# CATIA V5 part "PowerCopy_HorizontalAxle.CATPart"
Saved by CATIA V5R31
Part number: HorizontalAxle
Bounding box of the stored display mesh (mm): x -30 to 30, y -5 to 5, z -4.99 to 4.99
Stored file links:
  C:\Users\patol451\OneDrive - Linköpings universitet\Nuvarande kurser\Exjobb\LampCATIA\PowerCopy_HorizontalAxle.CATPart
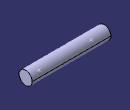
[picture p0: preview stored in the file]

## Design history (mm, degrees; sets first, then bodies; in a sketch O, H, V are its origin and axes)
Parameters
  diameter = 10 mm
  extraLength_OneSide = 10 mm
Set1 "References"
  Point1 "AxlePointLeft": (-20, 0, 0)
  Point2 "AxlePointRight": (20, 0, 0)
Set2 "Placement"
  Point3 "PlacementPoint1": type OnCurve, Support Line1, Ratio 0.5
  Point4 "PlacementPoint2": (0, 0, 0), relative to Point1
Set3 "Output"
  Point5 "OutputPoint1": (0, 0, 0), relative to Point1
  Point6 "OutputPoint2": (0, 0, 0), relative to Point2
  Point7 "OutputPoint3": type OnCurve, Support Line1, Ratio 0.5
Set4
  Line1: type PtPt, FirstPoint Point2, SecondPoint Point1
  Plane1: type Normal, Curve Line1, Ratio 0
  Circle1: type CenterAxis, Start 0, End 180, Pt Project1, Axis Line2, Radius 5 {= diameter /2}
  Plane2: type OffsetPt, RefPlane Plane1, RefPoint Point2
  Plane3: type Offset, RefPlane Plane2, Offset 10 {= extraLength_OneSide}, reversed
  Project1: ToProject Point2, Support Plane3
  Symmetry1: Reference Plane1, ToTransfor Project1
  Line2: type PtPt, FirstPoint Project1, SecondPoint Symmetry1
Body1 (main body)
  Rib1: profile Circle1, centre curve Line2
